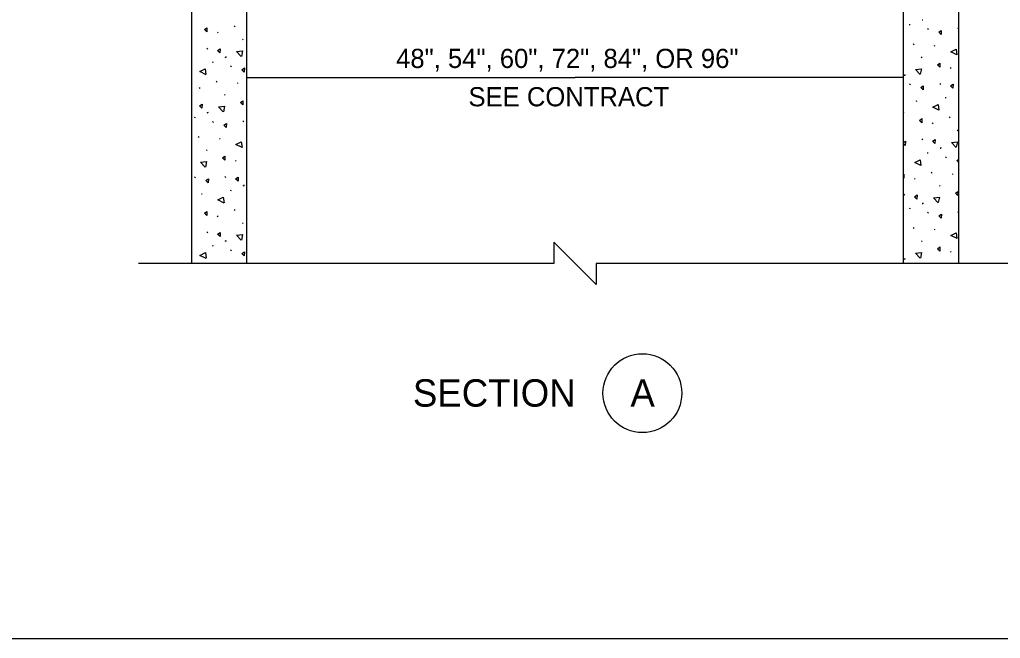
# Model space of a CAD drawing. Extents: x 99862 to 103151, y 100000 to 102076.
# Drawn here: x 100979 to 101696, y 100000 to 100451 of the extents above; entities that cross this region are included whole.
import ezdxf

# ---------------------------------------------------------------- set-up
doc = ezdxf.new("R2010")
doc.units = 0
for name, color, linetype in [('Level 1', 7, 'Continuous'), ('Level 15', 7, 'Continuous'), ('Level 20', 7, 'Continuous'), ('Level 7', 7, 'Continuous')]:
    doc.layers.add(name, color=color, linetype=linetype)

msp = doc.modelspace()

# ---------------------------------------------------------------- linework, layer by layer
at = {"layer": 'Level 1'}
msp.add_lwpolyline([(99862, 99999.5), (103151, 99999.5), (103151, 102075.5), (99862, 102075.5)], close=True, dxfattribs=at)
at = {"layer": 'Level 15'}
for p in [(101145.1, 100409.08), (101625.1, 100409.08)]:
    msp.add_line(p, (101385.1, 100409.08), dxfattribs=at)
msp.add_lwpolyline([(101706.68, 100273.34), (101400.58, 100273.34), (101400.58, 100257.86), (101369.61, 100288.83), (101369.61, 100273.34), (101066.18, 100273.34)], dxfattribs=at)
at = {"layer": 'Level 20'}
msp.add_circle((101434.22, 100178.55), 28.8, dxfattribs=at)
at = {"layer": 'Level 7'}
for p, q in [((101145.1, 100573.34), (101145.1, 100273.34)), ((101625.1, 100273.34), (101625.1, 100573.34)), ((101105.1, 100273.34), (101105.1, 100533.34)), ((101665.1, 100533.34), (101665.1, 100273.34)), ((101136.66, 100446.13), (101136.01, 100446.71)), ((101629.04, 100447.9), (101629.83, 100447.74)), ((101638.59, 100451.18), (101639.21, 100451.35)), ((101124.37, 100441.63), (101123.72, 100442.21)), ((101643.23, 100444.16), (101642.58, 100444.74)), ((101665.1, 100444.67), (101664.71, 100445.02)), ((101142.64, 100436.62), (101141.99, 100437.21)), ((101632.69, 100433.02), (101632.04, 100433.6)), ((101647.5, 100432.31), (101648.12, 100432.48)), ((101116.73, 100429.91), (101116.08, 100430.5)), ((101129.42, 100423.83), (101130.03, 100424)), ((101129.72, 100424.11), (101130.34, 100424.28)), ((101638.67, 100423.51), (101638.02, 100424.1)), ((101119.87, 100420.56), (101120.66, 100420.4)), ((101134.06, 100416.81), (101133.41, 100417.4)), ((101625.44, 100410.72), (101626.06, 100410.89)), ((101625.75, 100411), (101626.36, 100411.17)), ((101659.85, 100415.7), (101659.2, 100416.28)), ((101123.52, 100405.67), (101122.87, 100406.26)), ((101138.33, 100404.97), (101138.95, 100405.14)), ((101630.09, 100403.7), (101629.44, 100404.29)), ((101652.21, 100403.98), (101651.56, 100404.57)), ((101111.22, 100401.17), (101110.57, 100401.75)), ((101129.5, 100396.17), (101128.85, 100396.75)), ((101664.9, 100397.9), (101665.1, 100397.96)), ((101634.36, 100391.86), (101634.98, 100392.03)), ((101655.35, 100394.63), (101656.14, 100394.47)), ((101116.27, 100383.37), (101116.89, 100383.55)), ((101116.58, 100383.65), (101117.19, 100383.82)), ((101625.52, 100383.06), (101625.1, 100383.44)), ((101106.72, 100380.1), (101107.51, 100379.94)), ((101120.91, 100376.36), (101120.26, 100376.94)), ((101143.04, 100376.64), (101142.39, 100377.22)), ((101646.7, 100375.24), (101646.05, 100375.83)), ((101659, 100379.74), (101658.35, 100380.33)), ((101664.98, 100370.24), (101664.33, 100370.82)), ((101110.37, 100365.22), (101109.72, 100365.8)), ((101125.19, 100364.51), (101125.8, 100364.68)), ((101639.07, 100363.53), (101638.42, 100364.11)), ((101116.35, 100355.71), (101115.7, 100356.3)), ((101642.2, 100354.18), (101642.99, 100354.01)), ((101651.75, 100357.45), (101652.37, 100357.62)), ((101652.05, 100357.72), (101652.67, 100357.89)), ((101137.53, 100347.9), (101136.88, 100348.48)), ((101656.39, 100350.43), (101655.74, 100351.01)), ((101645.85, 100339.29), (101645.2, 100339.87)), ((101660.67, 100338.58), (101661.28, 100338.76)), ((101107.77, 100335.9), (101107.12, 100336.49)), ((101129.9, 100336.18), (101129.25, 100336.77)), ((101633.56, 100334.79), (101632.91, 100335.37)), ((101112.04, 100324.06), (101112.66, 100324.23)), ((101133.03, 100326.83), (101133.82, 100326.67)), ((101142.58, 100330.1), (101143.2, 100330.27)), ((101142.88, 100330.38), (101143.5, 100330.55)), ((101625.92, 100323.07), (101625.27, 100323.66)), ((101651.83, 100329.78), (101651.18, 100330.37)), ((101638.61, 100316.99), (101639.22, 100317.16)), ((101638.91, 100317.27), (101639.53, 100317.44)), ((101136.68, 100311.94), (101136.03, 100312.53)), ((101629.06, 100313.72), (101629.85, 100313.56)), ((101643.25, 100309.97), (101642.6, 100310.56)), ((101665.1, 100310.5), (101664.72, 100310.84)), ((101124.39, 100307.44), (101123.73, 100308.02)), ((101142.66, 100302.44), (101142.01, 100303.02)), ((101116.75, 100295.73), (101116.1, 100296.31)), ((101632.71, 100298.83), (101632.06, 100299.42)), ((101647.52, 100298.13), (101648.14, 100298.3)), ((101129.43, 100289.65), (101130.05, 100289.82)), ((101129.74, 100289.92), (101130.35, 100290.09)), ((101638.69, 100289.33), (101638.04, 100289.91)), ((101119.89, 100286.37), (101120.67, 100286.21)), ((101134.08, 100282.63), (101133.43, 100283.21)), ((101659.86, 100281.51), (101659.21, 100282.1)), ((101145.1, 100273.34), (101105.1, 100273.34)), ((101665.1, 100273.34), (101625.1, 100273.34)), ((101625.46, 100276.53), (101626.08, 100276.71)), ((101625.76, 100276.81), (101626.38, 100276.98))]:
    msp.add_line(p, q, dxfattribs=at)
for points in [[(101116.01, 100442.49), (101114.23, 100444.19), (101116.04, 100445.47), (101116.01, 100442.49)], [(101652.58, 100440.47), (101650.8, 100442.17), (101652.62, 100443.44), (101652.58, 100440.47)], [(101125.66, 100427.2), (101123.88, 100428.9), (101125.69, 100430.18), (101125.66, 100427.2)], [(101141.22, 100424.48), (101137.65, 100428.16), (101142.2, 100428.64), (101141.25, 100424.56)], [(101664.06, 100425.69), (101659.45, 100427.93), (101663.56, 100429.93), (101664.06, 100425.78)], [(101651.49, 100416.56), (101649.71, 100418.26), (101651.52, 100419.54), (101651.49, 100416.56)], [(101115.44, 100411.16), (101110.83, 100413.4), (101114.93, 100415.41), (101115.43, 100411.25)], [(101143.41, 100413.12), (101141.63, 100414.82), (101143.44, 100416.1), (101143.41, 100413.12)], [(101637.25, 100411.37), (101633.68, 100415.05), (101638.22, 100415.53), (101637.27, 100411.45)], [(101639.44, 100400.01), (101637.66, 100401.71), (101639.47, 100402.99), (101639.44, 100400.01)], [(101661.14, 100401.27), (101659.35, 100402.97), (101661.17, 100404.25), (101661.14, 100401.27)], [(101112.51, 100386.75), (101110.73, 100388.44), (101112.55, 100389.72), (101112.51, 100386.75)], [(101128.07, 100384.02), (101124.51, 100387.7), (101129.05, 100388.19), (101128.1, 100384.11)], [(101142.32, 100389.22), (101140.54, 100390.92), (101142.35, 100392.19), (101142.32, 100389.22)], [(101650.91, 100385.23), (101646.3, 100387.47), (101650.41, 100389.48), (101650.91, 100385.32)], [(101130.27, 100372.67), (101128.48, 100374.36), (101130.3, 100375.64), (101130.27, 100372.67)], [(101638.35, 100376.11), (101636.56, 100377.81), (101638.38, 100379.08), (101638.35, 100376.11)], [(101141.74, 100357.89), (101137.13, 100360.12), (101141.24, 100362.13), (101141.74, 100357.97)], [(101625.1, 100361.67), (101626.33, 100362.53), (101626.29, 100359.55)], [(101626.29, 100359.55), (101625.1, 100360.69)], [(101647.99, 100360.82), (101646.21, 100362.52), (101648.02, 100363.79), (101647.99, 100360.82)], [(101663.55, 100358.09), (101659.99, 100361.77), (101664.53, 100362.26), (101663.58, 100358.18)], [(101114.93, 100343.57), (101111.36, 100347.25), (101115.91, 100347.73), (101114.96, 100343.65)], [(101129.17, 100348.76), (101127.39, 100350.46), (101129.21, 100351.74), (101129.17, 100348.76)], [(101637.77, 100344.78), (101633.16, 100347.01), (101637.27, 100349.02), (101637.77, 100344.86)], [(101665.1, 100347.35), (101663.96, 100348.44), (101665.1, 100349.23)], [(101625.1, 100338.53), (101625.23, 100338.63), (101625.2, 100335.65)], [(101117.12, 100332.21), (101115.34, 100333.91), (101117.15, 100335.19), (101117.12, 100332.21)], [(101138.82, 100333.47), (101137.04, 100335.17), (101138.85, 100336.45), (101138.82, 100333.47)], [(101625.2, 100335.65), (101625.1, 100335.75)], [(101664.65, 100322.83), (101662.87, 100324.53), (101664.69, 100325.81), (101664.65, 100322.83)], [(101128.6, 100317.43), (101123.99, 100319.67), (101128.09, 100321.68), (101128.59, 100317.52)], [(101634.85, 100320.36), (101633.06, 100322.06), (101634.88, 100323.34), (101634.85, 100320.36)], [(101650.41, 100317.64), (101646.84, 100321.32), (101651.39, 100321.8), (101650.43, 100317.72)], [(101116.03, 100308.31), (101114.25, 100310.01), (101116.06, 100311.28), (101116.03, 100308.31)], [(101652.6, 100306.28), (101650.82, 100307.98), (101652.63, 100309.26), (101652.6, 100306.28)], [(101125.67, 100293.02), (101123.89, 100294.72), (101125.71, 100295.99), (101125.67, 100293.02)], [(101664.08, 100291.5), (101659.47, 100293.74), (101663.57, 100295.75), (101664.07, 100291.59)], [(101141.23, 100290.29), (101137.67, 100293.97), (101142.21, 100294.46), (101141.26, 100290.38)], [(101115.45, 100276.98), (101110.84, 100279.21), (101114.95, 100281.22), (101115.45, 100277.06)], [(101143.43, 100278.94), (101141.64, 100280.64), (101143.46, 100281.91), (101143.43, 100278.94)], [(101637.26, 100277.18), (101633.7, 100280.86), (101638.24, 100281.35), (101637.29, 100277.27)], [(101651.51, 100282.38), (101649.72, 100284.08), (101651.54, 100285.35), (101651.51, 100282.38)]]:
    msp.add_lwpolyline(points, dxfattribs=at)

# ---------------------------------------------------------------- texts
at = {"layer": 'Level 20'}
msp.add_text('48", 54", 60", 72", 84", OR 96"', height=14, rotation=360, dxfattribs=at).set_placement((101254.32, 100416.08))
for s, height, p in [('SEE CONTRACT', 14, (101307.18, 100388.08)), ('SECTION', 20, (101266.58, 100168.73)), ('A', 20, (101425.49, 100168.73))]:
    msp.add_text(s, height=height, dxfattribs=at).set_placement(p)

doc.saveas('drawing.dxf')
